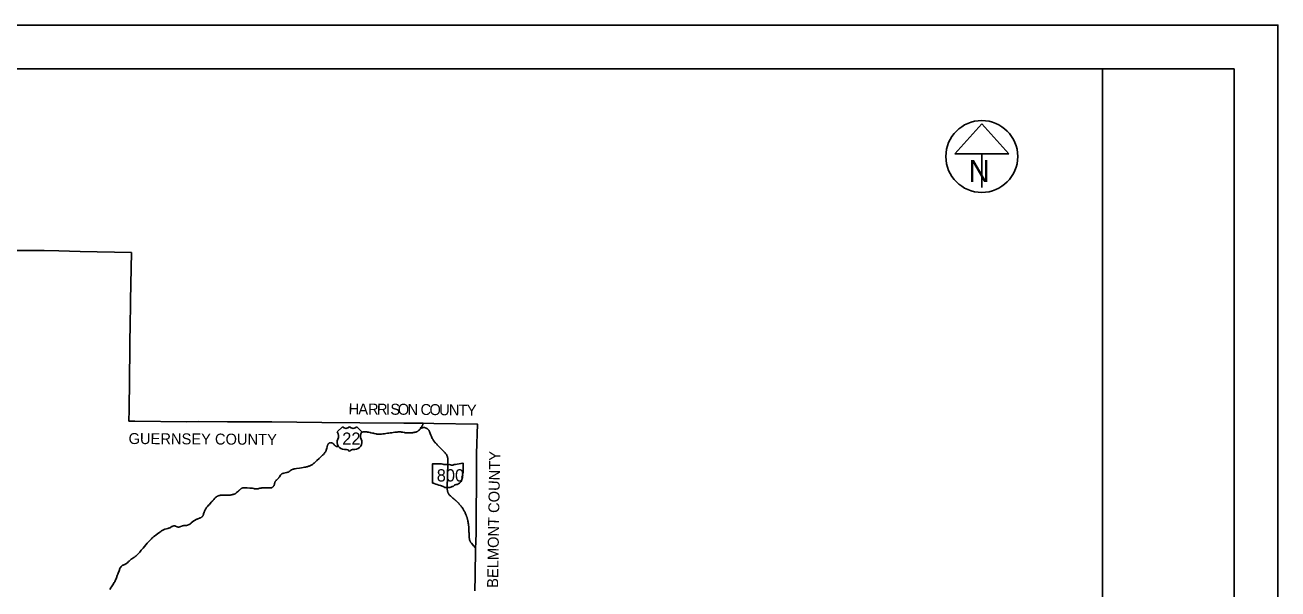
# Model space of a CAD drawing. Extents: x 1913970 to 2397567, y 78841 to 829347.
# Drawn here: x 2283311 to 2397567, y 777872 to 829347 of the extents above; entities that cross this region are included whole.
import ezdxf

# ---------------------------------------------------------------- set-up
doc = ezdxf.new("R2010")
doc.units = 0
for name, color, linetype in [('GM_X_County', 7, 'Continuous'), ('GM_X_County_Text', 7, 'Continuous'), ('GM_X_State_Location', 7, 'Continuous'), ('GM_X_State_Route', 7, 'Continuous'), ('GM_X_State_Shield', 7, 'Continuous'), ('GM_X_US_Location', 7, 'Continuous'), ('GM_X_US_Route', 7, 'Continuous'), ('GM_X_US_Shield', 7, 'Continuous'), ('SH_Border', 7, 'Continuous'), ('SH_Cut_Line', 7, 'Continuous'), ('SH_Masking', 7, 'Continuous'), ('SH_Text', 7, 'Continuous'), ('UT_P_Electric', 7, 'Continuous')]:
    doc.layers.add(name, color=color, linetype=linetype)

msp = doc.modelspace()

# ---------------------------------------------------------------- linework, layer by layer
at = {"layer": 'GM_X_County'}
msp.add_lwpolyline([(2281956, 808767), (2284041, 808770), (2285053, 808757), (2286394, 808725), (2288328, 808685), (2293016, 808573), (2292939, 804219), (2292926, 803905), (2292919, 803207), (2292907, 802587), (2292795, 794221), (2292778, 793200), (2293328, 793192), (2298034, 793131), (2299170, 793148), (2301762, 793132), (2303151, 793126), (2305817, 793127), (2310373, 793081), (2313829, 793046), (2317868, 792998), (2319608, 793009), (2320574, 792972), (2324571, 792926), (2324488, 790229), (2324467, 787489), (2324446, 784838), (2324439, 782996), (2324423, 782189), (2324401, 781598), (2324369, 779084), (2324336, 777711)], dxfattribs=at)
at = {"layer": 'GM_X_State_Route'}
msp.add_line((2319608, 793009), (2319609, 793021), dxfattribs=at)
for points in [[(2319371, 792533), (2319417, 792598), (2319493, 792706), (2319524, 792755), (2319548, 792795), (2319564, 792828), (2319576, 792855), (2319588, 792889), (2319598, 792927), (2319603, 792957), (2319608, 793009)], [(2324402, 781596), (2324362, 781646), (2324319, 781699), (2324258, 781773), (2324217, 781823), (2324155, 781895), (2324012, 782061), (2323965, 782119), (2323946, 782145), (2323919, 782182), (2323906, 782204), (2323894, 782227), (2323883, 782251), (2323874, 782272), (2323866, 782293), (2323860, 782311), (2323854, 782330), (2323850, 782345), (2323846, 782360), (2323843, 782374), (2323841, 782386), (2323838, 782399), (2323836, 782411), (2323834, 782424), (2323833, 782433), (2323832, 782446), (2323830, 782455), (2323830, 782465), (2323828, 782477), (2323826, 782500), (2323825, 782526), (2323823, 782555), (2323821, 782584), (2323820, 782601), (2323819, 782627), (2323818, 782640), (2323815, 782679), (2323813, 782712), (2323811, 782757), (2323809, 782780), (2323808, 782813), (2323807, 782822), (2323804, 782865), (2323801, 782914), (2323798, 782963), (2323796, 783005), (2323794, 783047), (2323793, 783086), (2323791, 783122), (2323790, 783154), (2323788, 783180), (2323787, 783200), (2323786, 783219), (2323786, 783232), (2323785, 783245), (2323784, 783264), (2323780, 783355), (2323774, 783460), (2323771, 783515), (2323768, 783574), (2323767, 783590), (2323764, 783646), (2323760, 783692), (2323753, 783751), (2323748, 783783), (2323745, 783800), (2323735, 783864), (2323728, 783910), (2323722, 783942), (2323715, 783984), (2323701, 784058), (2323692, 784103), (2323683, 784145), (2323674, 784183), (2323651, 784275), (2323642, 784307), (2323632, 784342), (2323624, 784367), (2323616, 784392), (2323605, 784426), (2323594, 784457), (2323580, 784495), (2323566, 784531), (2323556, 784558), (2323548, 784576), (2323533, 784612), (2323505, 784679), (2323484, 784729), (2323481, 784736), (2323449, 784807), (2323435, 784838), (2323405, 784900), (2323370, 784970), (2323337, 785031), (2323295, 785105), (2323267, 785150), (2323221, 785221), (2323159, 785314), (2323117, 785373), (2323076, 785428), (2323052, 785460), (2323044, 785470), (2323017, 785503), (2322992, 785533), (2322975, 785554), (2322939, 785596), (2322913, 785625), (2322889, 785652), (2322876, 785666), (2322862, 785681), (2322845, 785701), (2322826, 785723), (2322804, 785747), (2322786, 785766), (2322751, 785801), (2322727, 785823), (2322717, 785832), (2322686, 785860), (2322668, 785875), (2322663, 785879), (2322641, 785899), (2322624, 785914), (2322606, 785929), (2322584, 785948), (2322559, 785970), (2322540, 785987), (2322517, 786006), (2322508, 786014), (2322486, 786033), (2322404, 786101), (2322335, 786159), (2322255, 786227), (2322157, 786310), (2322101, 786359), (2322061, 786398), (2322028, 786434), (2321997, 786472), (2321964, 786516), (2321941, 786552), (2321925, 786580), (2321904, 786620), (2321891, 786650), (2321877, 786687), (2321863, 786730), (2321850, 786777), (2321835, 786838), (2321826, 786879), (2321819, 786927), (2321815, 786966), (2321812, 787018), (2321810, 787129), (2321811, 787267), (2321812, 787305), (2321814, 787401), (2321818, 787585), (2321821, 787689), (2321828, 787886), (2321832, 788027), (2321836, 788184), (2321838, 788299), (2321840, 788407), (2321841, 788449), (2321843, 788525), (2321846, 788610), (2321850, 788725), (2321854, 788853), (2321857, 788977), (2321864, 789167), (2321867, 789298), (2321868, 789400), (2321868, 789538), (2321869, 789636), (2321866, 789705), (2321863, 789748), (2321852, 789823), (2321845, 789862), (2321835, 789906), (2321822, 789947), (2321805, 789994), (2321782, 790045), (2321761, 790089), (2321736, 790132), (2321712, 790171), (2321683, 790211), (2321657, 790245), (2321645, 790261), (2321615, 790296), (2321569, 790343), (2321551, 790359), (2321398, 790520), (2321324, 790595), (2321264, 790655), (2321197, 790723), (2321123, 790797), (2321029, 790893), (2320962, 790961), (2320902, 791021), (2320848, 791078), (2320729, 791201), (2320685, 791249), (2320645, 791296), (2320612, 791337), (2320579, 791381), (2320552, 791422), (2320517, 791477), (2320483, 791537), (2320441, 791615), (2320401, 791697), (2320363, 791777), (2320334, 791846), (2320303, 791922), (2320255, 792054), (2320223, 792144), (2320200, 792205), (2320180, 792254), (2320158, 792299), (2320141, 792331), (2320121, 792365), (2320098, 792397), (2320081, 792418), (2320061, 792440), (2320039, 792460), (2320012, 792480), (2319979, 792501), (2319948, 792520), (2319898, 792546), (2319859, 792564), (2319826, 792578), (2319791, 792589), (2319762, 792596), (2319726, 792602), (2319693, 792604), (2319666, 792603), (2319633, 792600), (2319614, 792597), (2319607, 792596), (2319584, 792592), (2319568, 792588), (2319537, 792579), (2319509, 792570), (2319479, 792558), (2319455, 792549), (2319444, 792543), (2319423, 792535), (2319414, 792532), (2319406, 792529), (2319394, 792527), (2319383, 792529), (2319371, 792533)]]:
    msp.add_lwpolyline(points, dxfattribs=at)
at = {"layer": 'GM_X_State_Shield'}
for p, q in [((2320454, 789264), (2320454, 787562)), ((2321302, 789293), (2320482, 789293)), ((2323255, 788445), (2323256, 788445)), ((2323256, 788445), (2323256, 789335))]:
    msp.add_line(p, q, dxfattribs=at)
for centre, major_axis, start_param, end_param in [((2320486, 789267), (32.5, 0), 1.7126934, 3.2834897), ((2321497, 789490), (315, 0), 4.042523, 4.731795), ((2321602, 788338), (1130, 0), 1.4047578, 1.6578581), ((2321858, 789276), (90.8, 0), 3.8360951, 5.1854146), ((2321992, 789079), (189, 0), 0.950623, 2.079405), ((2322235, 789349), (227, 0), 4.0815608, 5.1457227), ((2322637, 788773), (598, 0), 1.6990114, 2.1078141), ((2322258, 791612), (2971, 0), 4.8143942, 5.0423688), ((2323249, 788380), (48.3, 0), 1.8839779, 3.6710726), ((2323225, 789339), (31.2, 0), 6.1411519, 7.9890352), ((2323222, 788442), (33.4, 0), 5.05454, 6.4181714), ((2320486, 787559), (32.7, 0), 3.00124, 4.5083009), ((2320491, 787733), (250, 0), 4.6659457, 4.8974612), ((2320542, 787464), (90.1, 0), 0.5192072, 1.6278991), ((2321680, 788993), (2146, 0), 4.1959971, 4.4889607), ((2321040, 786798), (671, 0), 0.8235189, 1.3235874), ((2322222, 787398), (240, 0), 4.9370686, 5.64225), ((2322737, 787085), (407, 0), 1.6476453, 2.4884337), ((2322424, 787959), (743, 0), 5.1017525, 6.4400178), ((2323367, 788073), (211, 0), 2.3877238, 3.2625369), ((2322941, 788267), (290, 0), 5.9346948, 6.6959481), ((2321766, 787456), (426, 0), 4.0264811, 4.9967352), ((2322013, 786868), (350, 0), 1.495662, 1.9409797), ((2322044, 787328), (227, 0), 4.6910439, 5.5073738), ((2322249, 787164), (63.9, 0), 1.1475842, 2.3151517)]:
    msp.add_ellipse(centre, major_axis=major_axis, ratio=0.8, start_param=start_param, end_param=end_param, dxfattribs=at)
at = {"layer": 'GM_X_US_Route'}
msp.add_line((2319608, 793009), (2319609, 793021), dxfattribs=at)
msp.add_lwpolyline([(2292600, 780226), (2292604, 780229), (2292654, 780271)], dxfattribs=at)
at = {"layer": 'GM_X_US_Shield'}
for p, q in [((2312250, 792667), (2311783, 792200)), ((2314024, 792200), (2313557, 792667)), ((2312437, 790612), (2312530, 790612)), ((2313277, 790612), (2313371, 790612))]:
    msp.add_line(p, q, dxfattribs=at)
for centre, radius, start, end in [((2311247, 791825), 654, 334.54712, 35.00093), ((2312577, 793000), 467, 225.573, 314.427), ((2313231, 793000), 467, 225.573, 314.427), ((2314560, 791825), 654, 144.99907, 205.45288), ((2312429, 791266), 654, 154.83192, 270.63826), ((2313378, 791266), 654, 269.36174, 25.16808), ((2312530, 790145), 467, 36.8699, 90), ((2313277, 790145), 467, 90, 143.1301)]:
    msp.add_arc(centre, radius, start, end, dxfattribs=at)
at = {"layer": 'SH_Border'}
msp.add_line((2381567, 657347), (2381567, 825347), dxfattribs=at)
msp.add_lwpolyline([(2137567, 825347), (2393567, 825347), (2393567, 657347), (2137567, 657347)], close=True, dxfattribs=at)
at = {"layer": 'SH_Cut_Line'}
msp.add_lwpolyline([(2125567, 653347), (2397567, 653347), (2397567, 829347), (2125567, 829347)], close=True, dxfattribs=at)
at = {"layer": 'SH_Masking'}
msp.add_circle((2370559, 817345), 3280, dxfattribs=at)
at = {"layer": 'SH_Text'}
for p, q in [((2370559, 820335), (2368099, 817605)), ((2373020, 817605), (2370559, 820335)), ((2368099, 817605), (2373020, 817605)), ((2370559, 817605), (2370559, 814511))]:
    msp.add_line(p, q, dxfattribs=at)
msp.add_circle((2370559, 817345), 3280, dxfattribs=at)
at = {"layer": 'UT_P_Electric'}
for points in [[(2319371, 792533), (2319417, 792598), (2319493, 792706), (2319524, 792755), (2319548, 792795), (2319564, 792828), (2319576, 792855), (2319588, 792889), (2319598, 792927), (2319603, 792957), (2319608, 793009)], [(2314006, 792173), (2314018, 792177), (2314050, 792187), (2314085, 792195), (2314125, 792202), (2314161, 792206), (2314203, 792209), (2314279, 792210), (2314355, 792209), (2314414, 792206), (2314479, 792201), (2314548, 792192), (2314603, 792184), (2314667, 792171), (2314776, 792148), (2314850, 792132), (2314869, 792128), (2315000, 792098), (2315090, 792078), (2315135, 792069), (2315315, 792028), (2315379, 792015), (2315434, 792005), (2315486, 791998), (2315538, 791994), (2315577, 791993), (2315613, 791993), (2315672, 791996), (2315760, 792004), (2315828, 792012), (2315935, 792026), (2316075, 792045), (2316202, 792061), (2316368, 792083), (2316491, 792099), (2316608, 792114), (2316751, 792134), (2316888, 792151), (2317021, 792169), (2317122, 792182), (2317252, 792198), (2317324, 792206), (2317383, 792211), (2317426, 792212), (2317469, 792212), (2317515, 792209), (2317567, 792204), (2317632, 792194), (2317762, 792170), (2317903, 792143), (2317984, 792130), (2318039, 792123), (2318104, 792116), (2318166, 792112), (2318229, 792110), (2318297, 792110), (2318366, 792112), (2318450, 792118), (2318548, 792126), (2318639, 792136), (2318708, 792145), (2318805, 792160), (2318862, 792171), (2318914, 792183), (2318961, 792195), (2318995, 792207), (2319025, 792218), (2319061, 792235), (2319098, 792255), (2319131, 792276), (2319135, 792279)], [(2319135, 792279), (2319163, 792299), (2319193, 792323), (2319205, 792334), (2319242, 792366), (2319278, 792403), (2319300, 792433), (2319322, 792465), (2319371, 792533)], [(2306061, 787475), (2306068, 787513), (2306076, 787548), (2306088, 787586), (2306102, 787623), (2306116, 787653), (2306132, 787681), (2306150, 787709), (2306170, 787736), (2306194, 787763), (2306226, 787796), (2306290, 787858), (2306323, 787889), (2306385, 787949), (2306411, 787977), (2306439, 788009), (2306466, 788046), (2306505, 788102), (2306609, 788261), (2306634, 788295), (2306654, 788318), (2306672, 788337), (2306692, 788354), (2306714, 788370), (2306739, 788385), (2306766, 788399), (2306797, 788411), (2306832, 788421), (2306914, 788443), (2307020, 788466), (2307139, 788493), (2307176, 788501), (2307262, 788522), (2307293, 788531), (2307326, 788543), (2307364, 788561), (2307403, 788585), (2307443, 788613), (2307491, 788652), (2307557, 788706), (2307603, 788738), (2307628, 788753), (2307655, 788767), (2307703, 788787), (2307744, 788800), (2307791, 788814), (2307865, 788830), (2307945, 788846), (2308055, 788865), (2308346, 788912), (2308533, 788941), (2308663, 788962), (2308798, 788985), (2308898, 789002), (2308969, 789015), (2309039, 789032), (2309108, 789051), (2309173, 789073), (2309232, 789095), (2309292, 789120), (2309351, 789147), (2309404, 789174), (2309464, 789207), (2309514, 789238), (2309568, 789275), (2309619, 789311), (2309672, 789354), (2309734, 789407), (2309801, 789470), (2309809, 789477), (2309932, 789594), (2310120, 789772), (2310285, 789927), (2310448, 790080), (2310516, 790147), (2310564, 790196), (2310608, 790244), (2310628, 790270), (2310663, 790317), (2310693, 790364), (2310715, 790403), (2310737, 790447), (2310757, 790492), (2310779, 790550), (2310801, 790618), (2310829, 790716), (2310862, 790846), (2310874, 790892), (2310887, 790945), (2310901, 790989), (2310914, 791023), (2310928, 791053), (2310945, 791082), (2310962, 791107), (2310978, 791127), (2310997, 791147), (2311017, 791164), (2311039, 791180), (2311066, 791197), (2311102, 791212), (2311132, 791220), (2311158, 791225), (2311185, 791228), (2311211, 791227), (2311238, 791225), (2311264, 791220), (2311290, 791213), (2311314, 791203), (2311338, 791191), (2311358, 791179), (2311380, 791164), (2311405, 791142), (2311430, 791116), (2311465, 791077), (2311513, 791019), (2311541, 790988), (2311567, 790963), (2311589, 790944), (2311613, 790927), (2311637, 790912), (2311663, 790898), (2311690, 790887), (2311721, 790877), (2311752, 790869), (2311781, 790865), (2311810, 790863), (2311838, 790863), (2311867, 790866), (2311896, 790871), (2311906, 790874)], [(2292654, 780271), (2292756, 780371), (2292803, 780417), (2292856, 780466), (2292911, 780513), (2292955, 780548), (2293000, 780581), (2293059, 780622), (2293142, 780675), (2293228, 780730), (2293268, 780757), (2293303, 780782), (2293362, 780828), (2293417, 780874), (2293473, 780925), (2293529, 780979), (2293584, 781036), (2293641, 781099), (2293768, 781245), (2293913, 781414), (2293989, 781500), (2294068, 781588), (2294459, 782043), (2294658, 782268), (2294710, 782323), (2294754, 782367), (2294845, 782459), (2294885, 782497), (2294962, 782570), (2294998, 782603), (2295060, 782657), (2295109, 782696), (2295281, 782828), (2295376, 782898), (2295612, 783066), (2295696, 783127), (2295758, 783170), (2295822, 783212), (2295867, 783239), (2295910, 783262), (2295946, 783279), (2295992, 783298), (2296045, 783317), (2296098, 783333), (2296200, 783360), (2296323, 783393), (2296395, 783415), (2296441, 783430), (2296483, 783447), (2296528, 783467), (2296574, 783491), (2296619, 783517), (2296695, 783563), (2296739, 783586), (2296772, 783601), (2296800, 783611), (2296829, 783618), (2296858, 783624), (2296901, 783629), (2296931, 783630), (2296957, 783629), (2296977, 783626), (2296997, 783621), (2297015, 783614), (2297032, 783607), (2297068, 783591), (2297101, 783577), (2297128, 783565), (2297155, 783553), (2297185, 783541), (2297202, 783535), (2297220, 783530), (2297239, 783527), (2297271, 783523), (2297287, 783521), (2297312, 783521), (2297341, 783524), (2297365, 783526), (2297393, 783531), (2297413, 783537), (2297430, 783542), (2297448, 783549), (2297489, 783565), (2297594, 783611), (2297611, 783616), (2297629, 783622), (2297679, 783634), (2297724, 783645), (2297771, 783654), (2297794, 783657), (2297817, 783659), (2297877, 783662), (2297920, 783663), (2297982, 783666), (2298003, 783666), (2298025, 783669), (2298045, 783672), (2298065, 783676), (2298106, 783687), (2298131, 783695), (2298157, 783704), (2298196, 783719), (2298226, 783732), (2298243, 783741), (2298270, 783754), (2298287, 783763), (2298336, 783791), (2298354, 783802), (2298371, 783813), (2298387, 783826), (2298412, 783846), (2298430, 783860), (2298472, 783896), (2298574, 783988), (2298616, 784024), (2298661, 784059), (2298716, 784099), (2298769, 784133), (2298819, 784164), (2298868, 784191), (2298900, 784207), (2298945, 784228), (2299000, 784250), (2299062, 784273), (2299223, 784329), (2299281, 784352), (2299328, 784373), (2299366, 784393), (2299382, 784403), (2299411, 784424), (2299436, 784445), (2299459, 784467), (2299481, 784492), (2299502, 784520), (2299521, 784551), (2299540, 784585), (2299557, 784623), (2299575, 784669), (2299596, 784731), (2299642, 784875), (2299662, 784934), (2299680, 784980), (2299704, 785038), (2299729, 785091), (2299755, 785141), (2299789, 785197), (2299825, 785252), (2299860, 785300), (2299900, 785352), (2299947, 785407), (2300016, 785486), (2300116, 785594), (2300197, 785684), (2300226, 785716), (2300285, 785782), (2300349, 785851), (2300355, 785857), (2300420, 785929), (2300436, 785946), (2300475, 785990), (2300512, 786031), (2300622, 786153), (2300658, 786191), (2300689, 786221), (2300722, 786249), (2300758, 786276), (2300802, 786307), (2300841, 786331), (2300878, 786352), (2300911, 786367), (2300951, 786383), (2300995, 786397), (2301036, 786408), (2301081, 786418), (2301127, 786425), (2301170, 786429), (2301216, 786432), (2301252, 786433), (2301324, 786432), (2301409, 786431), (2301521, 786429), (2301594, 786428), (2301721, 786427), (2301806, 786429), (2301874, 786432), (2301940, 786438), (2302008, 786446), (2302095, 786459), (2302176, 786473), (2302240, 786486), (2302300, 786502), (2302356, 786518), (2302396, 786532), (2302432, 786547), (2302461, 786561), (2302490, 786578), (2302519, 786597), (2302545, 786617), (2302601, 786663), (2302670, 786723), (2302769, 786810), (2302774, 786814), (2302850, 786881), (2302857, 786888), (2302923, 786946), (2302970, 786987), (2303023, 787032), (2303047, 787049), (2303058, 787057), (2303073, 787065), (2303083, 787071), (2303096, 787077), (2303105, 787081), (2303115, 787084), (2303125, 787087), (2303138, 787090), (2303149, 787092), (2303164, 787094), (2303182, 787095), (2303207, 787097), (2303256, 787098), (2303289, 787097), (2303341, 787096), (2303472, 787092), (2303555, 787090), (2303803, 787084), (2303809, 787083), (2303888, 787081), (2303937, 787077), (2303990, 787070), (2304041, 787060), (2304172, 787031), (2304230, 787020), (2304282, 787012), (2304327, 787008), (2304369, 787007), (2304415, 787008), (2304467, 787011), (2304519, 787017), (2304570, 787025), (2304635, 787038), (2304728, 787058), (2304847, 787083), (2304902, 787093), (2304964, 787101), (2305019, 787107), (2305075, 787110), (2305131, 787111), (2305216, 787108), (2305347, 787102), (2305495, 787094), (2305593, 787090), (2305645, 787089), (2305684, 787091), (2305723, 787096), (2305748, 787101), (2305773, 787107), (2305801, 787117), (2305827, 787128), (2305853, 787142), (2305880, 787160), (2305906, 787179), (2305928, 787198), (2305948, 787219), (2305969, 787244), (2305989, 787274), (2306006, 787302), (2306020, 787330), (2306033, 787360), (2306042, 787388), (2306050, 787419), (2306059, 787464), (2306061, 787475)], [(2291037, 777821), (2291135, 777976), (2291170, 778031), (2291200, 778078), (2291254, 778165), (2291318, 778264), (2291435, 778453), (2291483, 778535), (2291524, 778613), (2291566, 778699), (2291609, 778794), (2291651, 778897), (2291723, 779086), (2291770, 779214), (2291814, 779326), (2291895, 779534), (2291966, 779728), (2291992, 779788), (2292002, 779810), (2292009, 779824), (2292019, 779843), (2292027, 779858), (2292038, 779876), (2292066, 779914), (2292083, 779934), (2292097, 779948), (2292115, 779965), (2292131, 779979), (2292147, 779992), (2292165, 780006), (2292186, 780019), (2292208, 780032), (2292234, 780045), (2292258, 780056), (2292324, 780080), (2292400, 780109), (2292453, 780134), (2292504, 780162), (2292554, 780194), (2292600, 780226)]]:
    msp.add_lwpolyline(points, dxfattribs=at)

# ---------------------------------------------------------------- texts
at = {"layer": 'GM_X_County_Text'}
for s, rotation, p in [('H', 359.59331, (2312814, 793806)), ('A', 359.5946, (2313699, 793799)), ('R', 359.59358, (2314583, 793793)), ('R', 359.59358, (2315397, 793787)), ('I', 359.59342, (2316211, 793782)), ('S', 359.59267, (2316620, 793779)), ('O', 359.59222, (2317298, 793774)), ('N', 359.53568, (2318182, 793768)), ('C', 359.31238, (2319369, 793757)), ('O', 359.1344, (2320182, 793748)), ('U', 359.0822, (2321066, 793734)), ('N', 359.08002, (2321950, 793720)), ('T', 359.07942, (2322835, 793706)), ('Y', 359.07997, (2323583, 793694)), ('GUERNSEY COUNTY', 359.64169, (2292750, 791104)), ('BELMONT COUNTY', 89.06707, (2326444, 777969))]:
    msp.add_text(s, height=1000, rotation=rotation, dxfattribs=at).set_placement(p)
at = {"layer": 'GM_X_State_Location'}
msp.add_text('800', height=1, rotation=0.00001, dxfattribs=at).set_placement((2321483, 787993))
for s in ['s', 'r']:
    msp.add_text(s, height=1, dxfattribs=at).set_placement((2321836, 788066))
at = {"layer": 'GM_X_State_Shield'}
msp.add_text('800', height=1120.7, dxfattribs=at).set_placement((2320853, 787682))
at = {"layer": 'GM_X_US_Location'}
for p in [(2312846, 791333), (2298432, 783655)]:
    msp.add_text('22', height=1, rotation=0.00001, dxfattribs=at).set_placement(p)
for s, p in [('0', (2313053, 791540)), ('/', (2313053, 791540)), ('0', (2298638, 783862)), ('/', (2298638, 783862))]:
    msp.add_text(s, height=1, dxfattribs=at).set_placement(p)
at = {"layer": 'GM_X_US_Shield'}
msp.add_text('22', height=1120.7, dxfattribs=at).set_placement((2312234, 791032))
at = {"layer": 'SH_Text'}
msp.add_text('N', height=2000, dxfattribs=at).set_placement((2369349, 815015))

doc.saveas('drawing.dxf')
